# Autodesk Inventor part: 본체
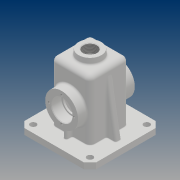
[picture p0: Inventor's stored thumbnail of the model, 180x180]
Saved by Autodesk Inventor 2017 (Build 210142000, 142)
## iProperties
Part Number: 본체
Material: 일반
Document SubType Name: Modeling
Designer: 20
Density: 1 g/cm^3
Appearance: 기본값
Mass: 292.115 g
Surface Area: 897.365 cm^2
Volume: 292.115 cm^3
Author: 20
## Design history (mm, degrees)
sketch "스케치2"
  geometry: L1 (-32.5, 32.5)-(32.5, 32.5); L2 (32.5, 32.5)-(32.5, -32.5); L3 (32.5, -32.5)-(-32.5, -32.5); L4 (-32.5, -32.5)-(-32.5, 32.5); L5 (-32.5, 32.5)-(32.5, -32.5); L6 (32.5, 32.5)-(-32.5, -32.5); 1 further point
  constraints: 12 end point, 2 midpoint, 2 parallel, 1 horizontal, 1 perpendicular
  dimensions: "d2" = 65 distance of L1.start L1.end; "d3" = 65 distance of L1.end L2.end
extrude "돌출1" new body sketch "스케치2" distance "d4" = 110; taper "d5" = 0 deg
sketch "스케치4"
  geometry: L1 (32.5, 0)-(-32.5, 0) reference; L2 (27.5, 0)-(-27.5, 0); L3 (-27.5, 0)-(-27.5, 105); L4 (-27.5, 105)-(27.5, 105); L5 (27.5, 105)-(27.5, 0); L6 (0, 105)-(0, 0); 2 further points
  constraints: 10 end point, 3 midpoint, 2 parallel, 2 point on line, 1 horizontal, 1 perpendicular
  dimensions: "d10" = 105 distance of L2.end L3.end; "d11" = 55 distance of L3.end L4.end
extrude "돌출3" cut sketch "스케치4" stored distance "d12" = 55; taper "d13" = 0 deg
sketch "스케치5"
  geometry: L1 (-60, -60)-(60, -60); L2 (60, -60)-(60, 60); L3 (60, 60)-(-60, 60); L4 (-60, 60)-(-60, -60); L5 (-60, -60)-(60, 60); L6 (60, -60)-(-60, 60); L7 (-27.5, 27.5)-(-27.5, -27.5) reference; L8 (-27.5, -27.5)-(27.5, -27.5) reference; L9 (27.5, 27.5)-(27.5, -27.5) reference; L10 (27.5, 27.5)-(-27.5, 27.5) reference; 1 further point
  constraints: 12 end point, 2 midpoint, 2 parallel, 1 horizontal, 1 perpendicular
  dimensions: "d14" = 120 distance of L3.end L1.start; "d15" = 120 distance of L2.end L3.end
extrude "돌출4" join sketch "스케치5" distance "d16" = 10; taper "d17" = 0 deg
sketch "스케치6"
  geometry: L1 (92.5, -110)-(-27.5, -110) reference; C1 r 27.5 at (32.5, -55); 2 further points
  constraints: 1 centre point, 1 midpoint, 1 vertical alignment
  dimensions: "d18" = 55 diameter of C1; "d19" = 55 distance from line of C1.centre L1
extrude "돌출5" join sketch "스케치6" distance "d20" = 15; taper "d21" = 0 deg
fillet "모깎기1" dims "d22" = 8
fillet "모깎기2" dims "d23" = 8
fillet "모깎기3" dims "d24" = 3
fillet "모깎기4" dims "d25" = 3
sketch "스케치7"
  geometry: C1 r 17.5 at (0, 0); C2 r 27.5 at (0, 0) reference; 1 further point
  constraints: 1 centre point, 1 concentric
  dimensions: "d26" = 35 diameter of C1
extrude "돌출6" cut sketch "스케치7" distance "d27" = 17; taper "d28" = 0 deg
sketch "스케치8"
  geometry: C1 r 15 at (0, 0); C2 r 17.5 at (0, 0) reference; 1 further point
  constraints: 1 centre point, 1 concentric
  dimensions: "d29" = 30 diameter of C1
extrude "돌출7" cut sketch "스케치8" stored distance "d30" = 17; taper "d31" = 0 deg
sketch "스케치9"
  geometry: C1 r 20 at (0, 0); 1 further point
  constraints: 1 centre point, 1 coincident
  dimensions: "d32" = 40 diameter of C1
extrude "돌출8" join sketch "스케치9" distance "d33" = 10; taper "d34" = -5 deg
hole "구멍1" diameter "d37" = 22.835; stored, may be unused: countersink angle "d41" = 90 deg, drill point angle "d43" = 118 deg; dims "d35" = 10, "d36" = 10, "d38" = 50, "d39" = 4, "d40" = 2, "d42" = 59.3
sketch "스케치11"
  geometry: L1 (60, -55)-(-60, -55) reference; C1 r 27.5 at (0, 0) reference; 3 further points
  constraints: 1 midpoint, 1 vertical alignment
  dimensions: "d44" = 21 distance of point (0, 21) C1.centre
hole "구멍2" sketch "스케치11" at (0, 21) diameter "d45" = 3.242; stored, may be unused: countersink angle "d49" = 90 deg, drill point angle "d51" = 118 deg; dims "d46" = 8, "d47" = 4, "d48" = 2, "d50" = 10
chamfer "모따기1" distance "d55" = 1; stored, may be unused: second distance "d56" = 2, angle "d57" = 45 deg
fillet "모깎기5" dims "d58" = 3
chamfer "모따기2" distance "d60" = 10; stored, may be unused: second distance "d61" = 2, angle "d62" = 45 deg
sketch "스케치12"
  geometry: L1 (-50, -60)-(50, -60) reference; L2 (60, -50)-(60, 50) reference; C1 r 5 at (47.5, -47.5); 1 further point
  constraints: 1 centre point
  dimensions: "d63" = 10 diameter of C1; "d64" = 12.5 distance from line of L1 C1.centre; "d65" = 12.5 distance from line of L2 C1.centre
extrude "돌출9" cut sketch "스케치12" stored distance "d66" = 10; taper "d67" = 0 deg
sketch "스케치13"
  geometry: L1 (-40.065, 55)-(-48, 10); L2 (-50, 10)-(-60, 10) reference; L3 (-60, 10)-(-60, 0) reference; 1 further point
  constraints: 2 end point, 1 point on line
  dimensions: "d74" = 12 distance from line of L3 L1.end; "d75" = 10 deg angle of L3 L1; "d76" = 45 distance from line of L2 L1.start
feature "리브1" sketch "스케치13" dims "d77" = 1, "d78" = 10, "d79" = 0, "d80" = 0, "d81" = 1, "d82" = 1
sketch "스케치14"
  geometry: L1 (-24.5, -27.5)-(24.5, -27.5) reference; L2 (-3, -27.5)-(3, -27.5); L3 (3, -27.5)-(3, -42.5); L4 (3, -42.5)-(-3, -42.5); L5 (-3, -42.5)-(-3, -27.5); L6 (0, -42.5)-(0, -27.5); 1 further point
  constraints: 10 end point, 2 midpoint, 2 parallel, 2 point on line, 1 horizontal, 1 perpendicular
  dimensions: "d83" = 6 distance of L3.end L4.end; "d84" = 15 distance of L2.end L3.end
extrude "돌출10" join sketch "스케치14" stored distance "d85" = 10; taper "d86" = 0 deg
fillet "모깎기7" dims "d87" = 3
fillet "모깎기8" dims "d88" = 3
fillet "모깎기9" dims "d89" = 3
fillet "모깎기10" dims "d90" = 3
fillet "모깎기11" dims "d91" = 3
fillet "모깎기12" dims "d92" = 1
node "작업 평면1"
sketch "스케치16"
  geometry: L1 (57, 0)-(57, 91) reference; L2 (43.625, -18)-(5.375, -18) reference; 2 further points
  constraints: 1 other
  dimensions: "d94" = 32.5 distance from line of L1 point (24.5, 8); "d95" = 26 distance from line of L2 point (24.5, 8)
feature "엠보싱1" sketch "스케치16" dims "d96" = 0.5, "d97" = 0
fillet "모깎기13" dims "d98" = 0.3
node "솔리드1"
mirror "미러1"
mirror "미러2"
pattern_circular "원형 패턴1" dims angle "d53" = 360 deg
mirror "미러3"
pattern_linear "직사각형 패턴1" dims "d70" = 95, "d73" = 95
mirror "미러4"
mirror "미러5"
node "투영된 루프1"
other parameters: "d93" = 64.25
